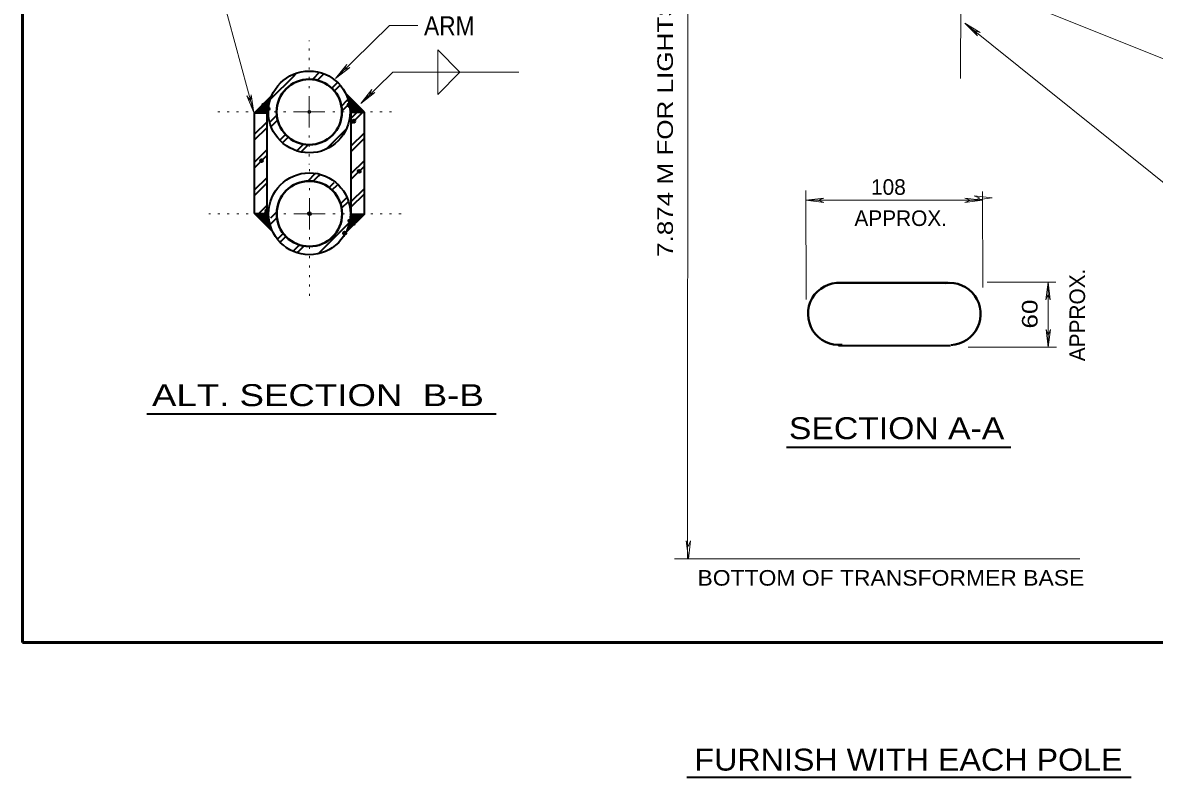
# Model space of a CAD drawing. Extents: x 312583 to 312854, y 144419 to 144597.
# Drawn here: x 312723.5 to 312778.8, y 144507 to 144543.8 of the extents above; entities that cross this region are included whole.
import ezdxf
from ezdxf.enums import TextEntityAlignment as Align

# ---------------------------------------------------------------- set-up
doc = ezdxf.new("R2010")
doc.units = 0
doc.header["$LTSCALE"] = 0.3
doc.header["$PDMODE"] = 32
doc.header["$PDSIZE"] = 0.15
doc.linetypes.add('DOTTED', pattern=[1.5, 0.3, -1.2])
doc.layers.add('1', color=7, linetype='Continuous', lineweight=35)
doc.layers.add('2', color=7, linetype='Continuous', lineweight=13)

msp = doc.modelspace()

# ---------------------------------------------------------------- linework, layer by layer
at = {"layer": '1', "lineweight": 53}
for p in [(312723.535, 144585.0846), (312849, 144513.591)]:
    msp.add_line(p, (312723.535, 144513.591), dxfattribs=at)
at = {"layer": '1'}
for p, q in [((312734.8584, 144539.4369), (312735.7248, 144540.3033)), ((312740.2174, 144539.4599), (312739.3358, 144540.3339)), ((312734.8584, 144534.5149), (312734.8584, 144539.4369)), ((312734.8584, 144539.4369), (312735.4641, 144539.4369)), ((312735.4641, 144534.5149), (312735.4641, 144539.4369)), ((312739.5734, 144534.4919), (312739.5734, 144539.4599)), ((312739.5734, 144539.4599), (312740.2174, 144539.4599)), ((312739.5734, 144538.9003), (312740.1331, 144539.4599)), ((312739.5734, 144539.1686), (312739.8571, 144539.4599)), ((312740.2174, 144534.4919), (312740.2174, 144539.4599)), ((312734.8584, 144538.3866), (312735.4641, 144538.9846)), ((312734.8584, 144538.1106), (312735.4641, 144538.7163)), ((312739.5734, 144537.8193), (312740.2174, 144538.4556)), ((312739.5734, 144537.5433), (312740.2174, 144538.1873)), ((312734.8584, 144537.0296), (312735.4641, 144537.6353)), ((312734.8584, 144536.7536), (312735.4641, 144537.3593)), ((312739.5734, 144536.4623), (312740.2174, 144537.0986)), ((312737.8331, 144536.4853), (312737.4344, 144536.0866)), ((312737.7488, 144536.4009), (312737.8254, 144536.4776)), ((312737.9174, 144536.5696), (312737.9098, 144536.5619)), ((312739.5734, 144536.1939), (312740.2174, 144536.8303)), ((312734.8584, 144535.6726), (312735.4641, 144536.2783)), ((312734.8584, 144535.4043), (312735.4641, 144536.0099)), ((312737.7104, 144536.0943), (312738.0401, 144536.4239)), ((312737.9864, 144536.3626), (312738.0554, 144536.4316)), ((312738.7224, 144536.0176), (312738.4924, 144535.7876)), ((312738.6304, 144535.6573), (312738.9218, 144535.9409)), ((312739.5734, 144535.1053), (312740.2174, 144535.7416)), ((312739.5734, 144534.8369), (312740.2174, 144535.4733)), ((312735.0578, 144534.5149), (312735.4641, 144534.9213)), ((312739.0674, 144535.0056), (312739.3664, 144535.3046)), ((312739.1211, 144534.7909), (312739.4354, 144535.1053)), ((312734.8584, 144534.5149), (312735.4641, 144534.5149)), ((312734.8584, 144534.5149), (312735.7631, 144533.6103)), ((312735.3261, 144534.5149), (312735.4641, 144534.6529)), ((312735.6098, 144533.9859), (312735.9548, 144534.3309)), ((312735.9394, 144534.5916), (312735.6404, 144534.2926)), ((312740.2174, 144534.4919), (312739.3434, 144533.6179)), ((312739.5734, 144534.4919), (312740.2174, 144534.4919)), ((312738.0094, 144532.5983), (312739.4814, 144534.0703)), ((312735.9701, 144533.2653), (312736.0238, 144533.3266)), ((312736.2614, 144533.5643), (312735.9778, 144533.2729)), ((312736.1004, 144533.1196), (312736.1541, 144533.1809)), ((312736.1158, 144533.1426), (312736.3764, 144533.3956)), ((312736.7368, 144532.6826), (312737.0434, 144532.9816)), ((312736.7368, 144532.6749), (312736.8058, 144532.7439)), ((312736.9361, 144532.6059), (312736.9898, 144532.6596)), ((312736.9438, 144532.6136), (312737.2581, 144532.9279)), ((312737.9711, 144532.5599), (312738.1091, 144532.6979)), ((312777.6471, 144507.0093), (312755.9614, 144507.0093))]:
    msp.add_line(p, q, dxfattribs=at)
at = {"layer": '1', "lineweight": 40}
for p, q in [((312739.3511, 144540.2956), (312739.3588, 144540.3109)), ((312734.9428, 144539.4369), (312735.6481, 144540.1423)), ((312735.0348, 144539.4369), (312735.6021, 144539.9966)), ((312735.1344, 144539.4369), (312735.5638, 144539.8663)), ((312739.3664, 144540.2189), (312739.4124, 144540.2649)), ((312739.3971, 144540.1499), (312739.4584, 144540.2113)), ((312739.4201, 144540.0886), (312739.5044, 144540.1653)), ((312739.4431, 144540.0196), (312739.5504, 144540.1193)), ((312739.4738, 144539.9429), (312739.5964, 144540.0733)), ((312739.4814, 144539.8663), (312739.6424, 144540.0273)), ((312739.4968, 144539.7896), (312739.6884, 144539.9813)), ((312739.5044, 144539.6976), (312739.7344, 144539.9353)), ((312739.5121, 144539.6133), (312739.7881, 144539.8893)), ((312739.5121, 144539.5213), (312739.8341, 144539.8356)), ((312739.5504, 144539.4676), (312739.8801, 144539.7896)), ((312735.2264, 144539.4369), (312735.5331, 144539.7436)), ((312735.3184, 144539.4369), (312735.5178, 144539.6439)), ((312735.4104, 144539.4369), (312735.5024, 144539.5289)), ((312739.6424, 144539.4676), (312739.9261, 144539.7436)), ((312739.7421, 144539.4599), (312739.9721, 144539.6976)), ((312739.8341, 144539.4599), (312740.0181, 144539.6516)), ((312739.9261, 144539.4599), (312740.0641, 144539.6056)), ((312740.0181, 144539.4599), (312740.1101, 144539.5596)), ((312740.1101, 144539.4599), (312740.1638, 144539.5136)), ((312740.2021, 144539.4599), (312740.2098, 144539.4599)), ((312734.8814, 144534.4919), (312734.8968, 144534.5149)), ((312734.9274, 144534.4459), (312734.9888, 144534.5149)), ((312734.9734, 144534.3999), (312735.0808, 144534.5149)), ((312735.0194, 144534.3539), (312735.1804, 144534.5149)), ((312735.0654, 144534.3079), (312735.2724, 144534.5149)), ((312735.1114, 144534.2619), (312735.3644, 144534.5149)), ((312735.1574, 144534.2159), (312735.4564, 144534.5149)), ((312735.2034, 144534.1699), (312735.5178, 144534.4766)), ((312735.2571, 144534.1163), (312735.5408, 144534.4076)), ((312735.3031, 144534.0703), (312735.5484, 144534.3233)), ((312735.3491, 144534.0243), (312735.5638, 144534.2389)), ((312739.3664, 144533.7253), (312740.1331, 144534.4919)), ((312739.4354, 144533.8863), (312740.0334, 144534.4919)), ((312739.4584, 144534.0013), (312739.9414, 144534.4919)), ((312739.4891, 144534.1316), (312739.8494, 144534.4919)), ((312739.5198, 144534.3463), (312739.6578, 144534.4919)), ((312739.5274, 144534.4459), (312739.5581, 144534.4843)), ((312739.5351, 144534.2696), (312739.7574, 144534.4919)), ((312735.3951, 144533.9783), (312735.5714, 144534.1546)), ((312735.4411, 144533.9323), (312735.5791, 144534.0703)), ((312735.4871, 144533.8863), (312735.6098, 144534.0013)), ((312735.5331, 144533.8403), (312735.6404, 144533.9399)), ((312735.5868, 144533.7943), (312735.6634, 144533.8709)), ((312735.6328, 144533.7406), (312735.6864, 144533.7943)), ((312735.6788, 144533.6946), (312735.7094, 144533.7329)), ((312735.7248, 144533.6486), (312735.7401, 144533.6639)), ((312768.707, 144531.1373), (312763.3864, 144531.1373)), ((312768.8144, 144528.063), (312763.3557, 144528.0706))]:
    msp.add_line(p, q, dxfattribs=at)
at = {"layer": '1'}
for centre in [(312737.5258, 144539.4733), (312737.5341, 144534.506)]:
    msp.add_circle(centre, 1.9965, dxfattribs=at)
for p in [(312735.3184, 144539.8203), (312735.3644, 144539.7666), (312735.4181, 144539.7206), (312735.4641, 144539.6746), (312739.4968, 144539.7896), (312739.5504, 144539.7436), (312739.5964, 144539.6976), (312735.5101, 144539.6286), (312739.6424, 144539.6516), (312739.6884, 144539.5979), (312739.7344, 144539.5519), (312739.7804, 144539.5059), (312739.6961, 144539.0229), (312735.1958, 144537.0909), (312739.9644, 144536.5773), (312735.4641, 144534.6529), (312737.5341, 144534.5073), (312739.5121, 144534.1546), (312739.5581, 144534.1086), (312739.6041, 144534.0626), (312739.6578, 144534.0166), (312739.2514, 144533.5643)]:
    msp.add_point(p, dxfattribs=at)
at = {"layer": '2'}
for p, q in [((312769.3127, 144541.1116), (312769.4277, 144575.1976)), ((312755.9957, 144517.6746), (312756.0034, 144564.265)), ((312782.8444, 144540.598), (312770.616, 144545.5123)), ((312781.8937, 144533.8743), (312769.5274, 144543.8103)), ((312769.5274, 144543.8103), (312770.1407, 144543.1893)), ((312769.5274, 144543.8103), (312770.271, 144543.3503)), ((312770.1407, 144543.1893), (312769.9874, 144543.4423)), ((312770.271, 144543.3503), (312769.9874, 144543.4423)), ((312743.7978, 144542.4959), (312743.7978, 144541.3459)), ((312743.7978, 144542.4959), (312744.8788, 144541.4073)), ((312738.8144, 144541.1083), (312739.3588, 144541.7906)), ((312738.8144, 144541.1083), (312739.5121, 144541.6373)), ((312739.3588, 144541.7906), (312739.2361, 144541.5223)), ((312739.5121, 144541.6373), (312739.2361, 144541.5223)), ((312741.5974, 144541.4073), (312740.0411, 144539.8893)), ((312747.7538, 144541.4073), (312741.5974, 144541.4073)), ((312743.7978, 144540.3263), (312743.7978, 144541.4073)), ((312743.7978, 144540.3263), (312744.8788, 144541.4073)), ((312734.6898, 144540.3109), (312734.6591, 144540.0196)), ((312734.8124, 144539.4446), (312734.6898, 144540.3109)), ((312740.0411, 144539.8893), (312740.5854, 144540.5716)), ((312740.0411, 144539.8893), (312740.7311, 144540.4183)), ((312740.5854, 144540.5716), (312740.4628, 144540.3033)), ((312740.7311, 144540.4183), (312740.4628, 144540.3033)), ((312734.4828, 144540.2573), (312734.6591, 144540.0196)), ((312734.8124, 144539.4446), (312734.4828, 144540.2573)), ((312737.5264, 144539.4753), (312737.5264, 144540.2419)), ((312734.8584, 144539.4369), (312734.8354, 144539.4676)), ((312737.5264, 144539.4753), (312736.7598, 144539.4753)), ((312737.5264, 144539.4753), (312737.5264, 144538.7086)), ((312737.5264, 144539.4753), (312738.2931, 144539.4753)), ((312761.7764, 144530.317), (312761.7687, 144535.6376)), ((312769.9874, 144535.377), (312770.2634, 144535.2696)), ((312770.8537, 144535.2773), (312769.9874, 144535.377)), ((312770.409, 144530.915), (312770.3937, 144535.5993)), ((312737.5341, 144534.5073), (312737.5341, 144535.2739)), ((312761.7687, 144535.1623), (312762.635, 144535.2696)), ((312761.7687, 144535.1623), (312762.635, 144535.2696)), ((312770.3937, 144535.1623), (312761.7687, 144535.1623)), ((312761.7687, 144535.1623), (312762.635, 144535.055)), ((312761.7687, 144535.1623), (312762.635, 144535.055)), ((312762.635, 144535.2696), (312762.359, 144535.1623)), ((312762.635, 144535.2696), (312762.359, 144535.1623)), ((312762.635, 144535.055), (312762.359, 144535.1623)), ((312762.635, 144535.055), (312762.359, 144535.1623)), ((312769.5274, 144535.2696), (312769.8034, 144535.1623)), ((312770.3937, 144535.1623), (312769.5274, 144535.2696)), ((312769.5274, 144535.2696), (312769.8034, 144535.1623)), ((312770.3937, 144535.1623), (312769.5274, 144535.2696)), ((312769.5274, 144535.055), (312769.8034, 144535.1623)), ((312770.3937, 144535.1623), (312769.5274, 144535.055)), ((312769.5274, 144535.055), (312769.8034, 144535.1623)), ((312770.3937, 144535.1623), (312769.5274, 144535.055)), ((312770.8537, 144535.2773), (312769.995, 144535.1623)), ((312769.995, 144535.1623), (312770.2634, 144535.2696)), ((312737.5341, 144534.5073), (312736.7674, 144534.5073)), ((312737.5341, 144534.5073), (312737.5341, 144533.7406)), ((312737.5341, 144534.5073), (312738.3008, 144534.5073)), ((312773.974, 144531.1756), (312770.6084, 144531.1756)), ((312773.5907, 144531.1756), (312773.4834, 144530.3093)), ((312773.5984, 144527.994), (312773.5907, 144531.1756)), ((312773.5907, 144531.1756), (312773.698, 144530.3093)), ((312773.4834, 144530.3093), (312773.5907, 144530.5853)), ((312773.698, 144530.3093), (312773.5907, 144530.5853)), ((312773.491, 144528.8603), (312773.5984, 144528.5843)), ((312773.5984, 144527.994), (312773.491, 144528.8603)), ((312773.7057, 144528.8603), (312773.5984, 144528.5843)), ((312773.5984, 144527.994), (312773.7057, 144528.8603)), ((312774.0047, 144527.994), (312769.6884, 144527.994)), ((312755.919, 144518.541), (312756.0264, 144518.265)), ((312756.034, 144517.6746), (312755.919, 144518.541)), ((312756.1337, 144518.541), (312756.0264, 144518.265)), ((312756.034, 144517.6746), (312756.1337, 144518.541)), ((312775.1317, 144517.6746), (312755.3594, 144517.667))]:
    msp.add_line(p, q, dxfattribs=at)
at = {"layer": '2', "linetype": 'DOTTED'}
for p, q in [((312737.5264, 144540.6253), (312737.5264, 144542.9636)), ((312736.3764, 144539.4753), (312732.7884, 144539.4753)), ((312738.6764, 144539.4753), (312741.8888, 144539.4753)), ((312737.5264, 144538.3253), (312737.5264, 144536.9146)), ((312737.5341, 144535.6573), (312737.5341, 144536.8226)), ((312736.3841, 144534.5073), (312732.6198, 144534.5073)), ((312738.6841, 144534.5073), (312742.0574, 144534.5073)), ((312737.5341, 144533.3573), (312737.5341, 144530.4593))]:
    msp.add_line(p, q, dxfattribs=at)
at = {"layer": '2', "lineweight": 35}
for p, q in [((312737.6951, 144541.0699), (312738.0478, 144541.4226)), ((312735.6251, 144540.0809), (312736.8134, 144541.2616)), ((312736.7904, 144541.2463), (312736.9208, 144541.3766)), ((312737.9251, 144541.0239), (312738.1858, 144541.2846)), ((312738.1704, 144541.2693), (312738.2394, 144541.3383)), ((312738.6228, 144540.6406), (312738.8681, 144540.8783)), ((312738.8528, 144540.8629), (312738.9064, 144540.9166)), ((312738.7531, 144540.4949), (312738.9984, 144540.7479)), ((312738.9754, 144540.7173), (312739.0368, 144540.7786)), ((312739.0981, 144539.7589), (312739.3818, 144540.0426)), ((312739.1288, 144539.5213), (312739.4278, 144539.8126)), ((312739.3588, 144540.0196), (312739.4278, 144540.0886)), ((312739.4124, 144539.7973), (312739.4814, 144539.8739)), ((312735.6634, 144538.7623), (312735.9854, 144539.0843)), ((312738.4924, 144537.7963), (312739.3434, 144538.6473)), ((312736.0851, 144538.0953), (312736.3688, 144538.3789)), ((312736.2231, 144537.9649), (312736.4991, 144538.2409)), ((312736.9131, 144537.5739), (312737.2504, 144537.9036)), ((312737.1278, 144537.5203), (312737.4804, 144537.8653)), ((312738.3544, 144537.6583), (312738.5538, 144537.8576)), ((312729.6002, 144524.7399), (312746.644, 144524.7399)), ((312771.7671, 144523.095), (312760.818, 144523.095))]:
    msp.add_line(p, q, dxfattribs=at)
at = {"layer": '2'}
for points in [[(312734.5364, 144546.2986), (312732.9724, 144546.2986), (312734.8124, 144539.4446)], [(312742.8241, 144543.6843), (312741.4441, 144543.6843), (312738.8144, 144541.1083)]]:
    msp.add_lwpolyline(points, dxfattribs=at)
at = {"layer": '2', "lineweight": 35}
msp.add_lwpolyline([(312735.6404, 144539.0076), (312735.5944, 144538.9693), (312735.9471, 144539.3143)], dxfattribs=at)
at = {"layer": '2', "lineweight": 40}
for centre in [(312737.5258, 144539.4733), (312737.5341, 144534.506)]:
    msp.add_circle(centre, 1.5972, dxfattribs=at)
for centre, radius, start, end in [((312763.3883, 144529.6219), 1.5174, 86.84375, 275.77798), ((312768.777, 144529.6177), 1.5192, 272.74469, 97.38753)]:
    msp.add_arc(centre, radius, start, end, dxfattribs=at)
at = {"layer": '2'}
for p in [(312739.4431, 144539.8279), (312737.5264, 144539.4753)]:
    msp.add_point(p, dxfattribs=at)

# ---------------------------------------------------------------- texts
at = {"layer": '2', "width": 1.25}
for s, p in [("7.874 M FOR LIGHTS TYPE 'C'", (312755.2773, 144532.3998)), ('60 ', (312773.075, 144528.9063))]:
    msp.add_text(s, height=0.76, rotation=90, dxfattribs=at).set_placement(p)
at = {"layer": '2'}
for s, height, width, p in [('ARM', 0.92, 0.9, (312743.1308, 144543.2166)), ('BOTTOM OF TRANSFORMER BASE', 0.76, 1.1, (312756.4763, 144516.3626))]:
    msp.add_text(s, height=height, dxfattribs=dict(at, width=width)).set_placement(p)
for s, p in [('108', (312764.948, 144535.4297)), ('APPROX.', (312764.1367, 144533.9097))]:
    msp.add_text(s, height=0.76, dxfattribs=at).set_placement(p)
msp.add_text('APPROX.', height=0.76, rotation=90, dxfattribs=at).set_placement((312775.3939, 144527.3103))
for s, width, p in [('ALT. SECTION  B-B', 1.25, (312737.9478, 144525.121)), ('SECTION A-A', 1.15, (312766.1959, 144523.5085)), ('FURNISH WITH EACH POLE', 1.1, (312766.774, 144507.339))]:
    msp.add_text(s, height=1.07, dxfattribs=dict(at, width=width)).set_placement(p, align=Align.CENTER)

doc.saveas('drawing.dxf')
